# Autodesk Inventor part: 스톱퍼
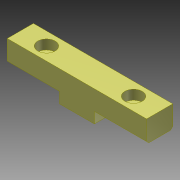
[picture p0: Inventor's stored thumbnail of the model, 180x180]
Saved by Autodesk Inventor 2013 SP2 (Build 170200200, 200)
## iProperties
Created: 2024-11
Part Number: 스톱퍼
Material: Generic
Document SubType Name: Modeling
Designer: a
Density: 1 g/cm^3
Author: a
변환 표준: STEP AP214IS
전처리기: Build: 200, Release: 2013 SP2 Update 6 - Date: Thu 07/17/2014
전송 단위: 밀리미터
불확실성: 0.01
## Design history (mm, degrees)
node "스톱퍼1"
node "솔리드1"
node "기준1"
